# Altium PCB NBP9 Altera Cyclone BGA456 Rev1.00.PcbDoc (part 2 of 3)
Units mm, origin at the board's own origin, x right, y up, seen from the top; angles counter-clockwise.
Board outline 69 x 80.99 mm, 6 copper layers (Top Layer, MidLayer1, InternalPlane1, InternalPlane2, MidLayer2, Bottom Layer); 105 components, 269 nets, 899 pads, 453 vias.
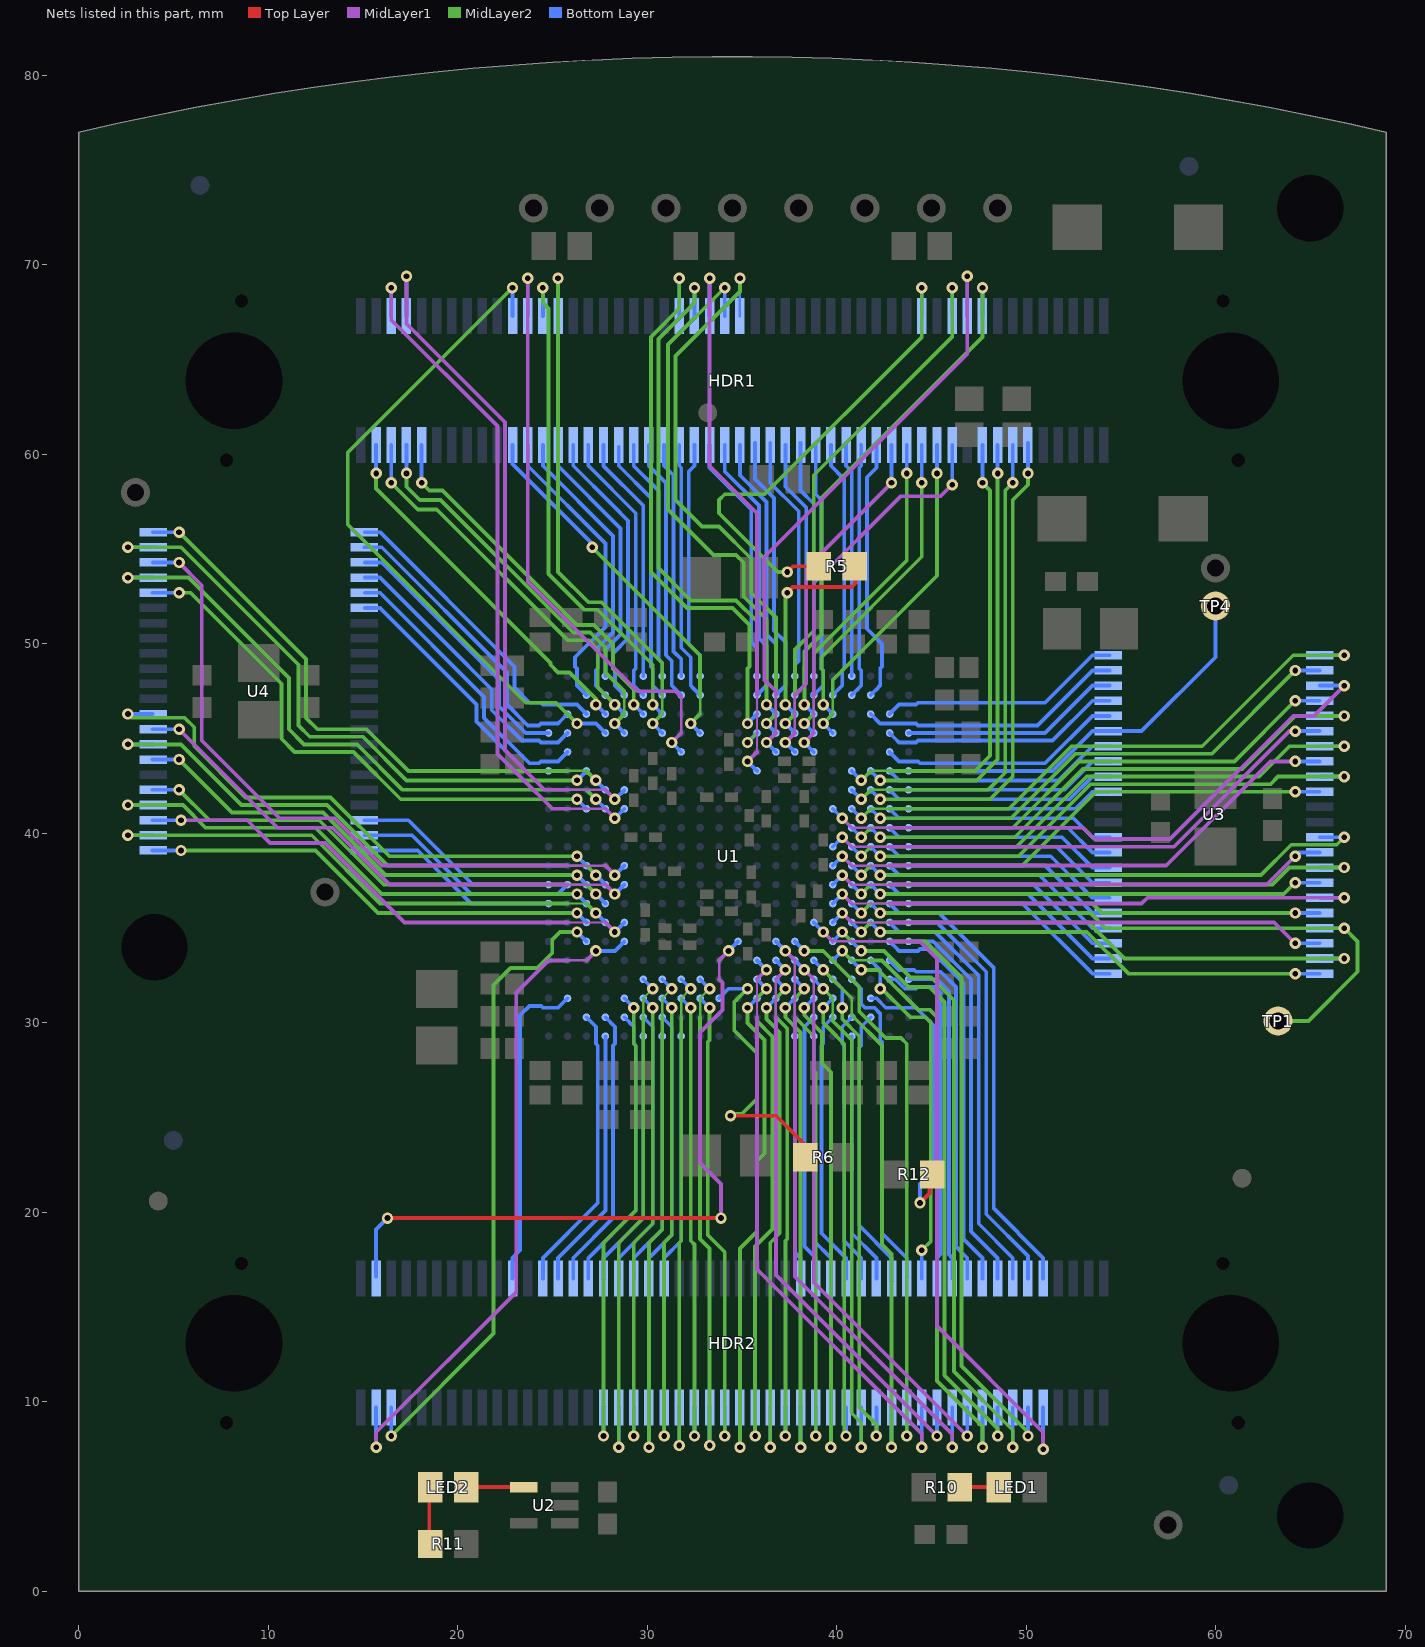
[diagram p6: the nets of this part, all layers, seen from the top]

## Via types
v1: diameter 0.6, hole 0.3, Top Layer to Bottom Layer, 453 vias

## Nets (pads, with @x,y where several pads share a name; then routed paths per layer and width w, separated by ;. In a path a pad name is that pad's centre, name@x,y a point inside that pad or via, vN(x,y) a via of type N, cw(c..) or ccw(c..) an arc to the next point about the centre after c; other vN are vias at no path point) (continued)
IO13: HDR2.33 U1.T3 | length 25.8
  MidLayer2 w0.2: v1(27.7,8.2) 27.7,18.4 29.4,20.1 29.4,28.8 29.3,28.9 v1(29.3,30.8)
  Bottom Layer w0.2: v1(27.7,8.2) HDR2.33@27.7,9.7 ; U1.T3@28.8,31.3 v1(29.3,30.8) v1@29.101,30.999
IO14: HDR2.35 U1.R4 | length 28
  MidLayer2 w0.127: 29.8,30.3 29.8,31.3 v1(30.3,31.8)
  MidLayer2 w0.2: v1(28.5,7.6) 28.5,18.4 29.8,19.7 29.8,30.3
  Bottom Layer w0.2: v1(28.5,7.6) HDR2.35@28.5,9.7 ; U1.R4@29.8,32.3 v1(30.3,31.8) v1@30.101,31.999
IO15: HDR2.37 U1.R3 | length 25.5
  MidLayer2 w0.2: v1(29.3,8.2) 29.3,18.4 30.3,19.4 v1(30.3,30.8)
  Bottom Layer w0.2: v1(29.3,8.2) HDR2.37@29.3,9.7 ; U1.R3@29.8,31.3 v1(30.3,30.8) v1@30.101,30.999
IO16: HDR2.39 U1.P4 | length 27.8
  MidLayer2 w0.127: 30.8,30.3 30.8,31.3 v1(31.3,31.8)
  MidLayer2 w0.2: v1(30.1,7.6) 30.1,18.4 30.8,19.1 30.8,30.3
  Bottom Layer w0.2: v1(30.1,7.6) HDR2.39@30.1,9.7 ; U1.P4@30.8,32.3 v1(31.3,31.8) v1@31.101,31.999
IO17: HDR2.41 U1.P3 | length 25.3
  MidLayer2 w0.2: v1(30.9,8.2) 30.9,18.4 31.3,18.8 v1(31.3,30.8)
  Bottom Layer w0.2: U1.P3@30.8,31.3 v1(31.3,30.8) v1@31.101,30.999 ; v1(30.9,8.2) HDR2.41@30.9,9.7
IO18: HDR2.43 U1.N4 | length 27.3
  MidLayer2 w0.127: 31.8,30.3 31.8,31.3 v1(32.3,31.8)
  MidLayer2 w0.2: v1(31.7,7.7) 31.7,18.4 31.8,18.5 31.8,30.3
  Bottom Layer w0.2: v1(31.7,7.7) HDR2.43@31.7,9.7 ; U1.N4@31.8,32.3 v1(32.3,31.8) v1@32.101,31.999
IO19: HDR2.45 U1.N3 | length 25.2
  MidLayer2 w0.2: v1(32.3,30.8) 32.3,18.5 32.5,18.3 v1(32.5,8.2)
  Bottom Layer w0.2: U1.N3@31.8,31.3 v1(32.3,30.8) v1@32.101,30.999 ; v1(32.5,8.2) HDR2.45@32.5,9.7
IO20: HDR2.47 U1.M4 | length 27.3
  MidLayer2 w0.127: 32.8,30.3 32.8,31.3 v1(33.3,31.8)
  MidLayer2 w0.203: 32.8,30.3 32.8,18.6 33.3,18.1 v1(33.3,7.7)
  Bottom Layer w0.2: U1.M4@32.8,32.3 v1(33.3,31.8) ; v1(33.3,7.7) HDR2.47@33.3,9.8
IO21: HDR2.49 U1.M3 | length 25.2
  MidLayer2 w0.203: v1(33.3,30.8) 33.3,29.1 33.2,29 33.2,18.8 34.1,17.9 v1(34.1,8.2)
  Bottom Layer w0.2: U1.M3@32.8,31.3 v1(33.3,30.8) ; v1(34.1,8.2) HDR2.49@34.1,9.7
IO22: HDR2.51 U1.J3 | length 26.9
  MidLayer2 w0.2: v1(34.9,7.6) 34.9,18.1 35.8,19 35.8,22.7 36.2,23.1 36.2,29.1 35.3,30 v1(35.3,30.8)
  Bottom Layer w0.2: v1(34.9,7.6) HDR2.51@34.9,9.7 ; v1(35.3,30.8) U1.J3@35.8,31.3
IO23: HDR2.53 U1.J4 | length 26.7
  MidLayer2 w0.127: 35.8,30.1 35.8,31.3
  MidLayer2 w0.2: v1(35.7,8.2) 35.7,18.2 36.6,19.1 36.6,29.3 35.8,30.1 ; 35.8,31.3 v1(36.3,31.8)
  Bottom Layer w0.2: v1(35.7,8.2) HDR2.53@35.7,9.7 ; U1.J4@35.8,32.3 v1(36.3,31.8)
IO24: HDR2.55 U1.H3 | length 26.8
  MidLayer2 w0.2: v1(36.3,30.8) 36.3,30.2 37,29.5 37,18.9 36.5,18.4 v1(36.5,7.6)
  Bottom Layer w0.2: v1(36.5,7.6) HDR2.55@36.5,9.7 ; v1@36.5,31 v1(36.3,30.8) U1.H3@36.8,31.3
IO25: HDR2.57 U1.H4 | length 26.6
  MidLayer2 w0.127: 36.8,30.3 36.8,31.3
  MidLayer2 w0.2: 36.8,30.3 37.4,29.7 37.4,18.6 37.3,18.5 v1(37.3,8.2) ; 36.8,31.3 v1(37.3,31.8)
  Bottom Layer w0.2: U1.H4@36.8,32.3 v1(37.3,31.8) v1@37.101,31.999 ; v1(37.3,8.2) HDR2.57@37.3,9.7
IO26: HDR2.59 U1.G3 | length 26.3
  MidLayer2 w0.2: v1(37.3,30.8) 37.3,30.3 38.1,29.5 v1(38.1,7.6)
  Bottom Layer w0.2: v1(37.3,30.8) U1.G3@37.8,31.3 ; v1(38.1,7.6) HDR2.59@38.1,9.7
IO27: HDR2.61 U1.G4 | length 26.8
  MidLayer2 w0.127: 37.8,30.3 37.8,31.3
  MidLayer2 w0.2: 37.8,30.3 38.8,29.3 38.8,27.5 38.9,27.4 v1(38.9,8.2) ; 37.8,31.3 v1(38.3,31.8)
  Bottom Layer w0.2: U1.G4@37.8,32.3 v1(38.3,31.8) v1@38.101,31.999 ; v1(38.9,8.2) HDR2.61@38.9,9.7
IO28: HDR2.63 U1.F3 | length 26.9
  MidLayer2 w0.2: v1(38.3,30.8) 38.3,30.4 39.225,29.475 39.225,27.875 39.7,27.4 v1(39.7,7.6)
  Bottom Layer w0.2: v1(38.3,30.8) v1@38.5,31 ; v1(38.3,30.8) U1.F3@38.8,31.3 ; v1(39.7,7.6) HDR2.63@39.7,9.7
IO29: HDR2.65 U1.E3 | length 25.6
  MidLayer2 w0.2: v1(39.3,30.8) 39.3,30 39.6,29.7 40.4,28.9 40.4,8.3 v1(40.5,8.2)
  Bottom Layer w0.2: v1@39.499,31 v1(39.3,30.8) U1.E3@39.8,31.3 ; v1(40.5,8.2) HDR2.65@40.5,9.7
IO30: HDR2.67 U1.F4 | length 28.1
  MidLayer2 w0.127: 39.8,30.3 39.8,31.3
  MidLayer2 w0.2: v1(39.3,31.8) 39.8,31.3 ; 39.8,30.3 39.8,30.1 40.8,29.1 40.8,9.4 41.3,8.9 v1(41.3,7.6)
  Bottom Layer w0.2: U1.F4@38.8,32.3 v1(39.3,31.8) v1@39.101,31.999 ; v1(41.3,7.6) HDR2.67@41.3,9.7
IO31: HDR2.69 U1.E4 | length 26.6
  MidLayer2 w0.2: v1(40.3,30.8) 40.3,30.2 41.2,29.3 41.2,9.7 42.1,8.8 v1(42.1,8.2)
  Bottom Layer w0.2: U1.E4@39.8,32.3 40.1,32 ; 40.101,31.999 40.3,31.8 v1(40.3,30.8) ; v1(42.1,8.2) HDR2.69@42.1,9.7
IO32: HDR2.71 U1.F5 | length 29.8
  MidLayer2 w0.127: 40.8,30.4 40.8,31.3
  MidLayer2 w0.2: v1(39.3,32.8) 40.8,31.3 ; 40.8,30.4 42.4,28.8 42.4,18.3 42.9,17.8 v1(42.9,7.6)
  Bottom Layer w0.2: U1.F5@38.8,33.3 v1(39.3,32.8) v1@39.101,32.999 ; v1(42.9,7.6) HDR2.71@42.9,9.7
IO33: HDR2.73 U1.G6 | length 31.6
  MidLayer2 w0.2: v1(38.3,33.8) 39.3,33.8 ; 39.1,33.8 39.3,33.8 ; v1(43.7,8.2) 43.7,28.9 43.4,29.2 42.6,29.2 41.2,30.6 41.2,31.9 40.3,32.8 39.3,33.8
  Bottom Layer w0.2: U1.G6@37.8,34.3 v1(38.3,33.8) v1@38.101,33.999 ; v1(43.7,8.2) HDR2.73@43.7,9.7
IO34: HDR2.75 U1.J5 | length 32.1
  MidLayer1 w0.127: 35.8,30.3 35.8,32.3
  MidLayer1 w0.2: 35.8,30.3 35.8,17 44.5,8.3 v1(44.5,7.6) ; 35.8,32.3 v1(36.3,32.8)
  Bottom Layer w0.2: U1.J5@35.8,33.3 v1(36.3,32.8) v1@36.101,32.999 ; v1(44.5,7.6) HDR2.75@44.5,9.7
IO35: HDR2.77 U1.H5 | length 30.8
  MidLayer1 w0.127: 36.8,30.3 36.8,32.3
  MidLayer1 w0.2: 36.8,30.3 36.8,16.7 v1(45.3,8.2) ; 36.8,32.3 v1(37.3,32.8)
  Bottom Layer w0.2: U1.H5@36.8,33.3 v1(37.3,32.8) v1@37.101,32.999 ; v1(45.3,8.2) HDR2.77@45.3,9.7
JIOA0: HDR1.3 U1.U18 | length 19.6
  MidLayer2 w0.2: v1@15.7,59.1 15.7,58.2 24.9,49 24.9,48.9 25.3,48.5 25.9,48.5 27.3,47.1 v1(27.3,46.8)
  Bottom Layer w0.2: v1@15.7,59.1 HDR1.3@15.7,60.5 ; v1(27.3,46.8) U1.U18@27.8,46.3
  other v1: 15.7,59
JIOA1: HDR1.5 U1.T18 | length 20.5
  MidLayer2 w0.2: v1(16.5,58.5) 17.9,57.1 18.9,57.1 25.8,50.2 26.9,50.2 27.4,49.7 27.4,47.7 v1(28.3,46.8)
  Bottom Layer w0.2: v1(16.5,58.5) HDR1.5@16.5,60.5 ; v1(28.3,46.8) U1.T18@28.8,46.3
JIOA2: HDR1.7 U1.T17 | length 21.5
  MidLayer2 w0.127: 28.8,46.3 28.8,47.3
  MidLayer2 w0.2: v1(17.3,59) 17.3,58.3 18,57.6 19.1,57.6 26.1,50.6 27,50.6 27.8,49.8 27.8,48.5 28.8,47.5 28.8,47.3 ; v1(28.3,45.8) 28.8,46.3
  Bottom Layer w0.2: v1(17.3,59) HDR1.7@17.3,60.5 ; v1(28.3,45.8) U1.T17@28.8,45.3
JIOA3: HDR1.9 U1.R18 | length 20
  MidLayer2 w0.2: v1(18.1,58.5) 18.5,58.1 19.2,58.1 26.3,51 27.2,51 28.2,50 28.2,48.7 29.3,47.6 v1(29.3,46.8)
  Bottom Layer w0.2: v1(18.1,58.5) HDR1.9@18.1,60.5 ; v1(29.3,46.8) U1.R18@29.8,46.3
JIOB0: HDR1.83 U1.D15 | length 24.9
  MidLayer2 w0.127: 41.8,43.3 42.8,43.3
  MidLayer2 w0.2: v1(41.3,42.8) 41.8,43.3 ; 42.8,43.3 47.3,43.3 48.1,44.1 48.1,58.1 v1(47.7,58.5)
  Bottom Layer w0.2: U1.D15@40.8,43.3 v1(41.3,42.8) v1@41.101,42.999 ; v1(47.7,58.5) HDR1.83@47.7,60.5
JIOB1: HDR1.85 U1.C15 | length 24.2
  MidLayer2 w0.2: v1(42.3,42.8) 47.4,42.8 48.5,43.9 v1(48.5,59)
  Bottom Layer w0.2: U1.C15@41.8,43.3 v1(42.3,42.8) v1@42.101,42.999 ; v1(48.5,59) HDR1.85@48.5,60.5
JIOB2: HDR1.87 U1.D14 | length 26.6
  MidLayer2 w0.127: 41.8,42.3 42.8,42.3
  MidLayer2 w0.2: v1(41.3,41.8) 41.8,42.3 ; 42.8,42.3 48,42.3 48.9,43.2 48.9,58.1 v1(49.3,58.5)
  Bottom Layer w0.2: U1.D14@40.8,42.3 v1(41.3,41.8) v1@41.101,41.999 ; v1(49.3,58.5) HDR1.87@49.3,60.5
JIOB3: HDR1.89 U1.C14 | length 26.4
  MidLayer2 w0.2: v1(42.3,41.8) 48.1,41.8 49.3,43 49.3,57.6 50.1,58.4 v1(50.1,59)
  Bottom Layer w0.2: U1.C14@41.8,42.3 v1(42.3,41.8) v1@42.101,41.999 ; v1(50.1,59) HDR1.89@50.1,60.6
KBCLOCK: HDR1.22 U1.U17 | length 35.8
  MidLayer2 w0.2: v1(22.9,68.8) 14.2,60.1 14.2,56.3 23.6,46.9 25.2,46.9 v1(26.3,45.8)
  Bottom Layer w0.2: HDR1.22@22.9,67.3 v1(22.9,68.8) ; v1(26.3,45.8) 27.3,45.8 U1.U17@27.8,45.3
KBDATA: HDR1.24 U1.N16 | length 31.9
  MidLayer1 w0.127: 31.8,45.3 31.8,47.2
  MidLayer1 w0.2: v1(23.7,69.3) 23.7,62.2 23.7,53.3 29.5,47.5 31.5,47.5 31.8,47.2 ; v1(31.3,44.8) 31.8,45.3
  Bottom Layer w0.2: HDR1.24@23.7,67.3 v1(23.7,69.3) ; v1(31.3,44.8) U1.N16@31.8,44.3
LCD_BCKL: HDR2.22 U1.W3 | length 17
  Bottom Layer w0.2: HDR2.22@22.9,16.5 22.9,17.6 23.3,18 23.3,30.4 23.8,30.9 24.4,30.9 24.5,30.8 25.3,30.8 U1.W3@25.8,31.3
LCD_E: HDR2.26 U1.V2 | length 15.2
  Bottom Layer w0.2: HDR2.26@24.5,16.5 24.5,17.6 27.2,20.3 27.4,20.5 27.4,28.8 27.3,28.9 27.3,29.8 U1.V2@26.8,30.3
LED0: HDR2.60 U1.G1 | length 13.2
  Bottom Layer w0.2: 37.8,28.7 U1.G1@37.8,29.3 ; 37.8,28.875 37.8,17.9 38.1,17.6 HDR2.60@38.1,16.4
LED1: HDR2.62 U1.F2 | length 14.3
  Bottom Layer w0.2: U1.F2@38.8,30.3 38.3,29.8 38.3,18.2 38.9,17.6 HDR2.62@38.9,16.5
LED2: HDR2.64 U1.F1 | length 13.5
  Bottom Layer w0.2: 38.8,28.6 U1.F1@38.8,29.3 ; 38.8,28.875 38.8,18.5 39.7,17.6 HDR2.64@39.7,16.4
LED3: HDR2.66 U1.E2 | length 14.6
  Bottom Layer w0.2: U1.E2@39.8,30.3 39.3,29.8 39.3,28.9 39.2,28.8 39.2,18.9 40.5,17.6 HDR2.66@40.5,16.5
LED4: HDR2.68 U1.D2 | length 14.4
  Bottom Layer w0.2: U1.D2@40.8,30.3 40.3,29.8 40.3,28.9 40.4,28.8 40.4,18.5 41.3,17.6 HDR2.68@41.3,16.5
LED5: HDR2.70 U1.D1 | length 13.4
  Bottom Layer w0.2: 40.8,28.8 U1.D1@40.8,29.3 ; 40.8,28.875 40.8,18.9 42.1,17.6 HDR2.70@42.1,16.5
LED6: HDR2.72 U1.C2 | length 14.9
  Bottom Layer w0.2: U1.C2@41.8,30.3 41.3,29.8 41.3,28.8 41.2,28.7 41.2,19.3 42.9,17.6 HDR2.72@42.9,16.4
LED7: HDR2.74 U1.D4 | length 17.2
  Bottom Layer w0.2: U1.D4@40.8,32.3 41.1,32 ; 41.101,31.999 41.3,31.8 41.3,31 41.5,30.8 42,30.8 42.3,30.5 42.3,29.1 42.4,29 42.4,18.9 43.7,17.6 HDR2.74@43.7,16.6
MOUSECLOCK: HDR1.26 U1.P18 | length 27
  MidLayer2 w0.2: v1(24.5,68.8) 24.5,68 24.8,67.7 24.8,53.7 26.7,51.8 27.4,51.8 30.3,48.9 v1(30.3,46.8)
  Bottom Layer w0.2: HDR1.26@24.5,67.3 24.5,67.4 v1(24.5,68.8) ; v1(30.3,46.8) U1.P18@30.8,46.3
MOUSEDATA: HDR1.28 U1.P17 | length 29.1
  MidLayer2 w0.127: 30.8,46.3 30.8,47.3
  MidLayer2 w0.2: v1(25.3,69.3) 25.3,66 25.3,53.8 26.9,52.2 27.6,52.2 30.8,49 30.8,47.3 ; v1(30.3,45.8) 30.8,46.3
  Bottom Layer w0.2: HDR1.28@25.3,67.3 v1(25.3,69.3) ; v1(30.3,45.8) U1.P17@30.8,45.3
NetLED1_1: LED1.1 R10.2 | length 2.1
  Top Layer w0.2: R10.2@46.5,5.5 LED1.1@48.6,5.5
NetLED2_1: LED2.1 R11.1 | length 3.1
  Top Layer w0.2: R11.1@18.5,2.4 LED2.1@18.5,5.5
NetLED2_2: LED2.2 U2.4 | length 3
  Top Layer w0.2: LED2.2@20.45,5.5 U2.4@23.5,5.5
NetR6_1: R6.1 U1.L3 | length 15.3
  Top Layer w0.2: v1(34.4,25.1) 36.8,25.1 38,23.9 38.4,23.5 R6.1@38.4,22.9
  MidLayer2 w0.2: v1@34.4,25.2 35,25.2 35.8,26 35.8,28.4 34.6,29.6 34.6,31.1 34.7,31.2 ; 34.725,31.2 34.725,31.225 v1(35.3,31.8)
  Bottom Layer w0.2: U1.L3@33.8,31.3 34.3,31.8 v1(35.3,31.8)
NetR12_1: R12.1 U1.C3 | length 15.3
  Top Layer w0.2: v1(44.4,20.5) 44.9,21 R12.1@44.9,22
  Bottom Layer w0.2: U1.C3@41.8,31.3 42.1,31.3 42.6,30.8 44.2,30.8 45.1,29.9 45.1,22.2 44.4,21.5 v1(44.4,20.5)
NEXUS_TCK: HDR1.82 U1.H16 | length 32.3
  MidLayer1 w0.127: 36.8,45.3 36.8,47.3
  MidLayer1 w0.2: v1(36.3,44.8) 36.8,45.3 ; 36.8,47.3 36.8,47.5 36.2,48.1 36.2,54.6 46.9,65.3 v1(46.9,69.4)
  Bottom Layer w0.2: v1(36.3,44.8) U1.H16@36.8,44.3 ; HDR1.82@46.9,67.3 v1(46.9,69.4)
NEXUS_TDI: HDR1.84 U1.F18 | length 28.1
  MidLayer2 w0.2: v1(38.3,46.8) 38.3,49.6 39.2,50.5 39.2,57.7 41.2,59.7 47.7,66.2 v1(47.7,68.8)
  Bottom Layer w0.2: v1(38.3,46.8) U1.F18@38.8,46.3 ; HDR1.84@47.7,67.3 v1(47.7,68.8)
NEXUS_TDO: HDR1.76 R5.1 | length 25.7
  Top Layer w0.2: v1(37.4,53.8) 37.7,54.1 R5.1@39,54.1
  MidLayer2 w0.2: v1(37.4,53.8) 36.9,53.8 33.8,56.9 33.8,57.6 34.1,57.9 36.2,57.9 44.5,66.2 v1(44.5,68.8)
  Bottom Layer w0.2: HDR1.76@44.5,67.3 v1(44.5,68.8)
NEXUS_TDO#: R5.2 U1.G18 | length 11.8
  Top Layer w0.2: v1(37.4,52.7) 37.7,53 40.8,53 41,53.2 R5.2@41,54.5
  MidLayer2 w0.2: v1(37.3,46.8) 37.3,52.6 v1(37.4,52.7)
  Bottom Layer w0.2: v1(37.3,46.8) U1.G18@37.8,46.3
NEXUS_TMS: HDR1.80 U1.G17 | length 29.1
  MidLayer2 w0.127: 37.8,46.3 37.8,47.3
  MidLayer2 w0.2: v1(37.3,45.8) 37.8,46.3 ; 37.8,47.3 37.8,49.7 38.8,50.7 38.8,58.9 46.1,66.2 v1(46.1,68.8)
  Bottom Layer w0.2: v1@37.5,45.6 v1(37.3,45.8) U1.G17@37.8,45.3 ; HDR1.80@46.1,67.3 v1(46.1,68.8)
RAM0_DATA0: HDR2.42 U1.N1 | length 13.4
  Bottom Layer w0.2: HDR2.42@30.9,16.5 30.9,17.6 31.8,18.5 31.8,28.875 ; 31.8,28.6 U1.N1@31.8,29.3
RAM0_DATA1: HDR2.40 U1.P2 | length 14.6
  Bottom Layer w0.2: HDR2.40@30.1,16.4 30.1,17.6 31.3,18.8 31.3,29.8 U1.P2@30.8,30.3
RAM0_DATA2: HDR2.38 U1.P1 | length 13.5
  Bottom Layer w0.2: HDR2.38@29.3,16.5 29.3,17.6 30,18.3 30.8,19.1 30.8,28.875 ; 30.8,28.8 U1.P1@30.8,29.3
RAM0_DATA3: HDR2.36 U1.R2 | length 14.8
  Bottom Layer w0.2: HDR2.36@28.5,16.5 28.5,17.6 30.3,19.4 30.3,27.5 30.3,29.8 U1.R2@29.8,30.3
RAM0_DATA4: HDR2.34 U1.R1 | length 13.6
  Bottom Layer w0.2: HDR2.34@27.7,16.5 27.7,17.6 29.8,19.7 29.8,28.875 ; 29.8,28.9 U1.R1@29.8,29.3
RAM0_DATA5: HDR2.32 U1.T2 | length 15.4
  Bottom Layer w0.2: HDR2.32@26.9,16.5 26.9,17.6 29.4,20.1 29.4,28.8 29.3,28.9 29.3,29.8 ; U1.T2@28.8,30.3 29.3,29.8 ; 29.101,29.999 29.3,29.8
RAM0_DATA6: HDR2.30 U1.U2 | length 15.2
  Bottom Layer w0.2: HDR2.30@26.1,16.5 26.1,17.6 28.2,19.7 28.2,28.8 28.3,28.9 28.3,29.8 ; U1.U2@27.8,30.3 28.3,29.8 ; 28.101,29.999 28.3,29.8
RAM0_DATA7: HDR2.28 U1.U1 | length 13.9
  Bottom Layer w0.2: HDR2.28@25.3,16.5 25.3,17.6 27.8,20.1 27.8,27.5 27.8,28.875 ; 27.8,28.8 U1.U1@27.8,29.3
RAM0_OE: HDR1.41 U1.N20 | length 12.6
  Bottom Layer w0.2: HDR1.41@30.9,60.5 30.9,59.4 31.2,59.1 31.4,58.9 31.4,49.6 31.8,49.2 U1.N20@31.8,48.3
RAM0_WE: HDR1.79 U1.F16 | length 20.9
  MidLayer1 w0.127: 38.8,45.3 38.8,47.3
  MidLayer1 w0.2: v1(38.3,44.8) 38.8,45.3 ; 38.8,47.3 38.8,53.2 43.4,57.8 45.5,57.8 v1(46.1,58.4)
  Bottom Layer w0.2: v1(38.3,44.8) U1.F16@38.8,44.3 ; v1(46.1,58.4) HDR1.79@46.1,60.5
RAM1_DATA0: HDR1.45 U1.M20 | length 12.6
  Bottom Layer w0.2: HDR1.45@32.5,60.5 32.5,59.4 32.2,59.1 32.2,50 32.8,49.4 32.8,49 U1.M20@32.8,48.3
RAM1_DATA1: HDR1.49 U1.J19 | length 14.5
  Bottom Layer w0.2: HDR1.49@34.1,60.5 34.1,59.1 35.9,57.3 35.9,50.3 36.3,49.9 36.3,47.8 36.2,47.7 ; U1.J19@35.8,47.3 36.2,47.7 ; 36.101,47.601 36.2,47.7
RAM1_DATA2: HDR1.53 U1.H19 | length 14.2
  Bottom Layer w0.2: HDR1.53@35.7,60.6 35.7,58.7 36.7,57.7 36.7,50.7 37.3,50.1 37.3,47.8 37.101,47.601 ; U1.H19@36.8,47.3 37.1,47.6
RAM1_DATA3: HDR1.57 U1.G19 | length 13.9
  Bottom Layer w0.2: HDR1.57@37.3,60.5 37.3,58.3 38.4,57.2 38.4,48.9 38.3,48.8 38.3,47.8 38.101,47.601 ; U1.G19@37.8,47.3 38.1,47.6
RAM1_DATA4: HDR1.55 U1.G20 | length 13
  Bottom Layer w0.2: HDR1.55@36.5,60.6 36.5,58.5 38,57 38,49.1 37.8,48.9 U1.G20@37.8,48.3
RAM1_DATA5: HDR1.51 U1.H20 | length 13
  Bottom Layer w0.2: HDR1.51@34.9,60.5 34.9,60.4 34.9,58.9 36.3,57.5 36.3,50.5 36.8,50 U1.H20@36.8,48.3
RAM1_DATA6: HDR1.47 U1.J20 | length 13.2
  Bottom Layer w0.2: HDR1.47@33.3,60.5 33.3,59.3 34.1,58.5 35.5,57.1 35.5,50.1 35.8,49.8 U1.J20@35.8,48.3
RAM1_DATA7: HDR1.43 U1.M19 | length 13.8
  Bottom Layer w0.2: HDR1.43@31.7,60.5 31.7,59.4 31.8,59.3 31.8,49.8 32.3,49.3 32.3,47.8 32.4,47.7 ; 32.5,47.6 32.4,47.7 ; U1.M19@32.8,47.3 32.4,47.7
RAM1_OE: HDR1.39 U1.N19 | length 13.9
  Bottom Layer w0.2: HDR1.39@30.1,60.5 30.1,59.4 31,58.5 31,49.4 31.3,49.1 31.3,47.8 U1.N19@31.8,47.3
RAM1_WE: HDR1.61 U1.F19 | length 13.7
  Bottom Layer w0.2: U1.F19@38.7,47.3 U1.F19@38.8,47.3 39.3,47.8 39.3,48.6 39.2,48.7 39.2,57.6 38.9,57.9 HDR1.61@38.9,60.5
RAM_ADDR0: HDR1.21 U1.M17 | length 20
  MidLayer2 w0.127: 32.8,46.3 32.8,47.3
  MidLayer2 w0.2: v1(27.1,55.1) 28,54.2 32.8,49.4 32.8,47.3 ; v1(32.3,45.8) 32.8,46.3
  Bottom Layer w0.2: HDR1.21@22.9,60.5 22.9,59.5 27.1,55.3 v1(27.1,55.1) ; v1@32.5,45.6 v1(32.3,45.8) U1.M17@32.8,45.3
RAM_ADDR1: HDR1.25 U1.U19 | length 15.3
  Bottom Layer w0.2: HDR1.25@24.5,60.5 24.5,59.4 28.2,55.7 28.2,50.6 27.4,49.8 27.4,48.7 27.3,48.6 27.3,47.8 U1.U19@27.8,47.3
RAM_ADDR2: HDR1.29 U1.T19 | length 15
  Bottom Layer w0.2: HDR1.29@26.1,60.5 26.1,59.4 28.2,57.3 29,56.5 29,50.3 28.2,49.5 28.2,48.7 28.3,48.6 28.3,47.8 U1.T19@28.8,47.3
RAM_ADDR3: HDR1.33 U1.R20 | length 13.1
  Bottom Layer w0.2: HDR1.33@27.7,60.5 27.7,59.4 29.8,57.3 U1.R20@29.8,48.3
RAM_ADDR4: HDR1.65 U1.D20 | length 12.3
  Bottom Layer w0.2: HDR1.65@40.5,60.5 40.5,59.4 40.8,59.1 U1.D20@40.8,48.3
RAM_ADDR5: HDR1.69 U1.C19 | length 14.1
  Bottom Layer w0.2: U1.C19@41.8,47.3 42.2,47.7 ; 42.101,47.601 42.3,47.8 42.3,48.7 42.4,48.8 42.4,50 41.6,50.8 41.6,58.8 42.1,59.3 HDR1.69@42.1,60.5
RAM_ADDR6: HDR1.73 U1.F17 | length 17.6
  MidLayer2 w0.127: 38.8,46.3 38.8,47.3
  MidLayer2 w0.2: v1(38.3,45.8) 38.8,46.3 ; 38.8,47.3 38.8,49.5 39.9,50.6 43.7,54.4 v1(43.7,59)
  Bottom Layer w0.2: v1(38.3,45.8) U1.F17@38.8,45.3 ; v1(43.7,59) HDR1.73@43.7,60.5
RAM_ADDR7: HDR1.77 U1.E17 | length 17.9
  MidLayer2 w0.127: 39.8,46.3 39.8,47.3
  MidLayer2 w0.2: v1(39.3,45.8) 39.8,46.3 ; 39.8,47.3 39.8,48.1 41.1,49.4 45.3,53.6 45.3,58.4 v1(45.3,59)
  Bottom Layer w0.2: v1(39.3,45.8) U1.E17@39.8,45.3 ; v1(45.3,59) HDR1.77@45.3,60.5
RAM_ADDR8: HDR1.75 U1.E18 | length 16.6
  MidLayer2 w0.2: v1(39.3,46.8) 39.3,48.6 39.2,48.7 39.2,49.3 44.5,54.6 v1@44.5,58.5
  Bottom Layer w0.2: v1(39.3,46.8) U1.E18@39.8,46.3 ; v1(44.5,58.5) HDR1.75@44.5,60.5
RAM_ADDR9: HDR1.71 U1.G16 | length 18.7
  MidLayer1 w0.127: 37.8,45.3 37.8,47.3
  MidLayer1 w0.2: v1(37.3,44.8) 37.8,45.3 ; 37.8,47.3 38.4,47.9 38.4,54 40.2,55.8 v1(42.9,58.5)
  Bottom Layer w0.2: v1(37.3,44.8) U1.G16@37.8,44.3 ; v1(42.9,58.5) HDR1.71@42.9,60.5
RAM_ADDR10: HDR1.67 U1.D19 | length 13.6
  Bottom Layer w0.2: U1.D19@40.8,47.3 41.2,47.7 ; 41.101,47.601 41.2,47.7 ; HDR1.67@41.3,60.5 41.3,59.4 41.2,59.3 41.2,48.7 41.3,48.6 41.3,47.8 41.2,47.7
RAM_ADDR11: HDR1.63 U1.E19 | length 13.7
  Bottom Layer w0.2: HDR1.63@39.7,60.5 39.7,59.4 40.4,58.7 40.4,48.7 40.3,48.6 40.3,47.8 U1.E19@39.8,47.3
RAM_ADDR12: HDR1.59 U1.F20 | length 12.6
  Bottom Layer w0.2: HDR1.59@38.1,60.6 38.1,58.1 38.8,57.4 U1.F20@38.8,48.3
RAM_ADDR13: HDR1.35 U1.P19 | length 14.1
  Bottom Layer w0.2: HDR1.35@28.5,60.4 28.5,59.4 30.2,57.7 30.2,48.8 30.3,48.7 30.3,47.8 U1.P19@30.8,47.3
RAM_ADDR14: HDR1.31 U1.R19 | length 14.5
  Bottom Layer w0.2: HDR1.31@26.9,60.5 26.9,59.4 29.4,56.9 29.4,48.7 29.3,48.6 29.3,47.8 U1.R19@29.8,47.3
RAM_ADDR15: HDR1.27 U1.U20 | length 13.9
  Bottom Layer w0.2: HDR1.27@25.3,60.5 25.3,59.4 28.6,56.1 28.6,50.5 27.8,49.7 U1.U20@27.8,48.3
RAM_ADDR16: HDR1.23 U1.V19 | length 15.8
  Bottom Layer w0.2: HDR1.23@23.7,60.5 23.7,59.4 27.8,55.3 27.8,50.9 26.2,49.3 26.2,48.8 26.3,48.7 26.3,47.8 U1.V19@26.8,47.3
RAM_CS: HDR1.37 U1.P20 | length 12.8
  Bottom Layer w0.2: HDR1.37@29.3,60.5 29.3,59.4 30.6,58.1 30.6,49.2 30.8,49 U1.P20@30.8,48.3
RED0: HDR1.6 U1.T13 | length 37
  MidLayer1 w0.127: 25.8,41.3 27.8,41.3
  MidLayer1 w0.2: v1(16.5,68.8) 16.5,67.1 22.1,61.5 22.1,44.2 23.4,42.9 25,41.3 25.8,41.3 ; 27.8,41.3 v1(28.3,40.8)
  Bottom Layer w0.2: HDR1.6@16.5,67.3 v1(16.5,68.8) ; v1@28.499,40.999 v1(28.3,40.8) U1.T13@28.8,41.3
RED1: HDR1.8 U1.T14 | length 37.1
  MidLayer1 w0.127: 25.8,42.3 27.8,42.3
  MidLayer1 w0.2: v1(17.3,69.4) 17.3,66.9 22.5,61.7 22.5,44.4 24.6,42.3 25.8,42.3 ; 27.8,42.3 v1(28.3,41.8)
  Bottom Layer w0.2: HDR1.8@17.3,67.3 v1(17.3,69.4) ; v1@28.499,41.999 v1(28.3,41.8) U1.T14@28.8,42.3
REF_CLK: HDR2.4 U1.K6 | length 37
  Top Layer w0.2: v1(16.3,19.7) v1(33.9,19.7)
  MidLayer1 w0.127: 33.8,32.3 33.8,33.3
  MidLayer1 w0.2: 33.8,32.3 33.975,32.125 33.975,30.675 32.8,29.5 32.8,22.6 33.9,21.5 v1(33.9,19.7) ; 33.8,33.3 v1(34.3,33.8)
  Bottom Layer w0.2: HDR2.4@15.7,16.6 15.7,19.1 v1(16.3,19.7) ; v1(34.3,33.8) U1.K6@34.8,34.3
SCL: HDR2.5 U1.V6 | length 34.2
  MidLayer2 w0.2: v1(16.5,8.2) 21.9,13.6 21.9,32 22.8,32.9 24.2,32.9 25,33.7 25,34.4 25.4,34.8 v1(26.3,34.8)
  Bottom Layer w0.2: v1(16.5,8.2) HDR2.5@16.5,9.7 ; v1(26.3,34.8) U1.V6@26.8,34.3
SDA: HDR2.3 U1.T6 | length 36
  MidLayer1 w0.127: 25.8,33.3 26.8,33.3
  MidLayer1 w0.2: v1(15.7,7.6) 15.7,8.4 23.1,15.8 23.1,31.6 24.8,33.3 25.8,33.3 ; 26.8,33.3 v1(27.3,33.8)
  Bottom Layer w0.2: v1(15.7,7.6) HDR2.3@15.7,9.7 ; v1(27.3,33.8) 28.3,33.8 U1.T6@28.8,34.3
SP0: HDR2.79 U1.H6 | length 32.9
  MidLayer1 w0.127: 37.8,30.3 37.8,33.3
  MidLayer1 w0.2: v1(37.3,33.8) 37.8,33.3 ; 37.8,30.3 37.8,16.6 46.1,8.3 v1(46.1,7.6)
  Bottom Layer w0.2: U1.H6@36.8,34.3 v1(37.3,33.8) v1@37.101,33.999 ; v1(46.1,7.6) HDR2.79@46.1,9.7
SP1: HDR2.81 U1.G5 | length 30.7
  MidLayer1 w0.127: 38.8,30.3 38.8,32.3
  MidLayer1 w0.2: v1(38.3,32.8) 38.8,32.3 ; 38.8,30.3 38.8,16.3 v1(46.9,8.2)
  Bottom Layer w0.2: U1.G5@37.8,33.3 v1(38.3,32.8) v1@38.101,32.999 ; v1(46.9,8.2) HDR2.81@46.9,9.7
SP2: HDR2.83 U1.D5 | length 31.8
  MidLayer2 w0.2: v1(41.3,32.8) 42.2,32.8 44.3,30.7 44.9,30.7 45.3,30.3 45.3,11.1 47.7,8.7 v1(47.7,7.6)
  Bottom Layer w0.2: U1.D5@40.8,33.3 v1(41.3,32.8) v1@41.101,32.999 ; v1(47.7,7.6) HDR2.83@47.7,9.7
SP3: HDR2.85 U1.E5 | length 32.8
  MidLayer2 w0.127: 40.8,33.3 41.8,33.3
  MidLayer2 w0.2: v1(40.3,33.8) 40.8,33.3 ; 41.8,33.3 42.4,33.3 43.3,32.4 43.8,31.9 44.9,31.9 45.7,31.1 45.7,11.4 48.5,8.6 v1(48.5,8.2)
  Bottom Layer w0.2: U1.E5@39.8,33.3 v1(40.3,33.8) ; v1(48.5,8.2) HDR2.85@48.5,9.7
SP4: HDR2.87 U1.D6 | length 33.9
  MidLayer2 w0.2: v1(41.3,33.8) 42.5,33.8 43.9,32.4 45,32.4 46.2,31.2 46.2,11.6 49.3,8.5 v1(49.3,7.6)
  Bottom Layer w0.2: U1.D6@40.8,34.3 v1(41.3,33.8) v1@41.101,33.999 ; v1(49.3,7.6) HDR2.87@49.3,9.7
SP5: HDR2.89 U1.E6 | length 35.2
  MidLayer2 w0.127: 40.8,34.3 42.8,34.3
  MidLayer2 w0.2: v1(40.3,34.8) 40.8,34.3 ; 42.8,34.3 44.7,34.3 46.6,32.4 46.6,11.9 50.1,8.4 v1(50.1,8.2)
  Bottom Layer w0.2: U1.E6@39.8,34.3 v1(40.3,34.8) ; v1(50.1,8.2) HDR2.89@50.1,9.7
SP6: HDR2.91 U1.F7 | length 38
  MidLayer1 w0.127: 39.8,34.3 42.8,34.3
  MidLayer1 w0.2: v1(39.3,34.8) 39.8,34.3 ; 42.8,34.3 44.4,34.3 45.3,33.4 45.3,14 50.9,8.4 v1(50.9,7.5)
  Bottom Layer w0.2: U1.F7@38.8,35.3 v1(39.3,34.8) v1@39.101,34.999 ; v1(50.9,7.5) HDR2.91@50.9,9.7
SP7: HDR2.90 U1.A7 | length 22.3
  Bottom Layer w0.2: U1.A7@43.8,35.3 45.3,35.3 47.9,32.7 47.9,19.9 50.1,17.7 HDR2.90@50.1,16.5
SP8: HDR2.92 U1.B8 | length 24.7
  Bottom Layer w0.2: U1.B8@42.8,36.3 43.3,35.8 ; 43.101,35.999 43.3,35.8 45.4,35.8 48.3,32.9 48.3,20.2 50.9,17.6 HDR2.92@50.9,16.5
SP9: HDR2.88 U1.B7 | length 22.6
  Bottom Layer w0.2: U1.B7@42.8,35.3 43.3,34.8 45.2,34.8 47.5,32.5 47.5,19.4 49.3,17.6 HDR2.88@49.3,16.5
SP10: HDR2.86 U1.A6 | length 20.5
  Bottom Layer w0.2: U1.A6@43.8,34.3 45.1,34.3 47.1,32.3 47.1,19 48.5,17.6 HDR2.86@48.5,16.5
SP11: HDR2.84 U1.B6 | length 21
  Bottom Layer w0.2: U1.B6@42.8,34.3 43.2,33.9 ; 43.101,33.999 43.3,33.8 44.3,33.8 44.4,33.9 44.9,33.9 46.7,32.1 46.7,18.6 47.7,17.6 HDR2.84@47.7,16.5
SP12: HDR2.82 U1.B5 | length 19.7
  Bottom Layer w0.2: U1.B5@42.8,33.3 43.3,32.8 44.1,32.8 44.2,32.7 45.5,32.7 46.3,31.9 46.3,18.2 46.9,17.6 HDR2.82@46.9,16.5
SP13: HDR2.80 U1.A4 | length 17.6
  Bottom Layer w0.2: U1.A4@43.8,32.3 45.3,32.3 45.93,31.67 45.93,17.77 46.1,17.6 HDR2.80@46.1,16.5
SP14: HDR2.78 U1.B4 | length 18.3
  Bottom Layer w0.2: U1.B4@42.8,32.3 43.1,32.3 43.6,31.8 44.2,31.8 44.3,31.9 45.2,31.9 45.5,31.6 45.5,17.8 45.3,17.6 HDR2.78@45.3,16.5
SP15: HDR2.76 U1.C5 | length 18.8
  MidLayer2 w0.2: v1@42.3,31.9 43.9,30.3 44.7,30.3 44.975,30.025 44.975,18.475 v1(44.5,18)
  Bottom Layer w0.2: U1.C5@41.8,33.3 42.3,32.8 v1@42.3,31.9 ; HDR2.76@44.5,16.5 44.5,16.6 v1(44.5,18)
  other v1: 42.3,31.8
SPI_CLK: HDR1.46 U1.J17 | length 30.8
  MidLayer2 w0.127: v1(35.3,44.8) 35.8,45.3 35.8,47.3
  MidLayer2 w0.2: v1(32.5,68.8) 32.5,68 30.6,66.1 30.6,54 32.3,52.3 34.7,52.3 35.8,51.2 35.8,47.3
  Bottom Layer w0.2: HDR1.46@32.5,67.3 v1(32.5,68.8) ; v1(35.3,44.8) U1.J17@35.8,45.3
SPI_DIN: HDR1.44 U1.J18 | length 30.4
  MidLayer2 w0.2: v1(31.7,69.3) 31.7,67.7 30.2,66.2 30.2,53.8 32.1,51.9 34.5,51.9 35.4,51 35.4,48.8 35.3,48.7 v1(35.3,45.8)
  Bottom Layer w0.2: HDR1.44@31.7,67.3 v1(31.7,69.3) ; v1(35.3,45.8) U1.J18@35.8,46.3
SPI_DOUT: HDR1.50 U1.H18 | length 28.6
  MidLayer2 w0.2: v1(34.1,68.8) 31.1,65.8 31.1,57.1 32.5,55.7 32.9,55.3 33.5,54.7 34.7,54.7 35.1,54.3 35.1,52.5 36.3,51.3 v1(36.3,46.8)
  Bottom Layer w0.2: HDR1.50@34.1,67.3 v1(34.1,68.8) ; v1@36.5,46.6 v1(36.3,46.8) U1.H18@36.8,46.3
SPI_MODE: HDR1.52 U1.H17 | length 30.5
  MidLayer2 w0.127: 36.8,46.3 36.8,47.3
  MidLayer2 w0.2: v1(34.9,69.3) 34.9,68.6 31.5,65.2 31.5,57.6 32.9,56.2 33.8,56.2 35.5,54.5 35.5,52.7 36.8,51.4 36.8,47.3 ; v1(36.3,45.8) 36.8,46.3
  Bottom Layer w0.127: HDR1.52@34.9,67.3 v1(34.9,69.3)
  Bottom Layer w0.2: v1(36.3,45.8) U1.H17@36.8,45.3
SPI_SEL: HDR1.48 U1.J15 | length 29.4
  MidLayer1 w0.127: 35.8,44.3 35.8,47.3
  MidLayer1 w0.2: v1(33.3,69.3) 33.3,59.4 35.8,56.9 35.8,47.3 ; v1(35.3,43.8) 35.8,44.3
  Bottom Layer w0.2: HDR1.48@33.3,67.3 v1(33.3,69.3) ; v1(35.3,43.8) U1.J15@35.8,43.3
SRAM0_A0: U1.A10 U3.5 | length 11.7
  Bottom Layer w0.2: U1.A10@43.8,38.3 44.4,38.3 ; 44.225,38.3 45.9,38.3 51,38.3 53.5,35.8 U3.5@54.3,35.8
SRAM0_A1: U1.B10 U3.4 | length 13.2
  Bottom Layer w0.2: U1.B10@42.8,38.3 43.3,37.8 ; 43.101,37.999 43.3,37.8 ; U3.4@54.4,35 53.5,35 50.7,37.8 43.3,37.8
SRAM0_A2: U1.A9 U3.3 | length 11.9
  Bottom Layer w0.2: U1.A9@43.8,37.3 50.4,37.3 53.5,34.2 U3.3@54.4,34.2
SRAM0_A3: U1.B9 U3.2 | length 13.2
  Bottom Layer w0.2: U1.B9@42.8,37.3 43.3,36.8 50.1,36.8 53.5,33.4 U3.2@54.4,33.4
SRAM0_A4: U1.A8 U3.1 | length 12.3
  Bottom Layer w0.2: U1.A8@43.8,36.3 44.4,36.3 ; 44.225,36.3 45.5,36.3 49.8,36.3 53.5,32.6 U3.1@54.4,32.6
SRAM0_A5: U1.C7 U3.44 | length 25.1
  MidLayer2 w0.2: v1(42.3,34.8) 53.2,34.8 55.4,32.6 v1(64.2,32.6)
  Bottom Layer w0.2: U1.C7@41.8,35.3 v1(42.3,34.8) v1@42.101,34.999 ; v1(64.2,32.6) U3.44@65.5,32.6
SRAM0_A6: U1.D7 U3.43 | length 28.8
  MidLayer2 w0.127: 41.8,35.3 42.8,35.3
  MidLayer2 w0.2: v1(41.3,34.8) 41.8,35.3 ; 42.8,35.3 53.3,35.3 55.2,33.4 v1(66.8,33.4)
  Bottom Layer w0.2: U1.D7@40.8,35.3 v1(41.3,34.8) v1@41.101,34.999 ; U3.43@65.5,33.4 v1(66.8,33.4)
SRAM0_A7: U1.E7 U3.42 | length 26.9
  MidLayer1 w0.127: 40.8,35.3 42.8,35.3
  MidLayer1 w0.2: v1(40.3,35.8) 40.8,35.3 ; 42.8,35.3 63.1,35.3 v1(64.2,34.2)
  Bottom Layer w0.2: U1.E7@39.8,35.3 v1(40.3,35.8) v1@40.101,35.601 ; v1(64.2,34.2) U3.42@65.5,34.2
SRAM0_A8: U1.B16 U3.18 | length 12.9
  Bottom Layer w0.2: U1.B16@42.8,44.3 43.3,43.8 44.3,43.8 44.4,43.7 51,43.7 53.5,46.2 U3.18@54.4,46.2
SRAM0_A9: U1.C12 U3.27 | length 29.4
  MidLayer2 w0.2: v1(42.3,39.8) 49.4,39.8 53,43.4 61.4,43.4 64.2,46.2 v1(66.8,46.2)
  Bottom Layer w0.2: U1.C12@41.8,40.3 v1(42.3,39.8) v1@42.101,39.999 ; U3.27@65.5,46.2 v1(66.8,46.2)
SRAM0_A10: U1.D12 U3.26 | length 28.2
  MidLayer2 w0.127: 41.8,40.3 42.8,40.3
  MidLayer2 w0.2: v1(41.3,39.8) 41.8,40.3 ; 42.8,40.3 49.3,40.3 52.8,43.8 61,43.8 v1(64.2,47)
  Bottom Layer w0.2: U1.D12@40.8,40.3 v1(41.3,39.8) v1@41.101,39.999 ; v1(64.2,47) U3.26@65.5,47
SRAM0_A11: U1.E13 U3.25 | length 32.6
  MidLayer1 w0.127: 40.8,40.3 42.8,40.3
  MidLayer1 w0.2: v1(40.3,40.8) 40.8,40.3 ; 42.8,40.3 53,40.3 53.6,39.7 57.6,39.7 64.1,46.2 65.2,46.2 v1(66.8,47.8)
  Bottom Layer w0.2: U1.E13@39.8,41.3 v1(40.3,40.8) v1@40.101,40.999 ; U3.25@65.5,47.8 v1(66.8,47.8)
SRAM0_A12: U1.C13 U3.24 | length 27.4
  MidLayer2 w0.2: v1(42.3,40.8) 49.2,40.8 52.6,44.2 59.8,44.2 v1(64.2,48.6)
  Bottom Layer w0.2: U1.C13@41.8,41.3 v1(42.3,40.8) v1@42.101,40.999 ; v1(64.2,48.6) U3.24@65.5,48.6
SRAM0_A13: U1.D13 U3.23 | length 31.4
  MidLayer2 w0.127: 41.8,41.3 42.8,41.3
  MidLayer2 w0.2: v1(41.3,40.8) 41.8,41.3 ; 42.8,41.3 49.1,41.3 52.4,44.6 59.3,44.6 64.1,49.4 v1(66.8,49.4)
  Bottom Layer w0.2: U1.D13@40.8,41.3 v1(41.3,40.8) v1@41.101,40.999 ; U3.23@65.5,49.4 v1(66.8,49.4)
  other v1: 41.3,40.8
SRAM0_A14: U1.B18 U3.22 | length 13.2
  Bottom Layer w0.2: U1.B18@42.8,46.3 43.3,46.8 ; 43.101,46.601 43.3,46.8 ; U3.22@54.4,49.4 53.5,49.4 51,46.9 44.3,46.9 44.2,46.8 43.3,46.8
SRAM0_A15: U1.C18 U3.21 | length 14.3
  Bottom Layer w0.2: U1.C18@41.8,46.3 42.3,45.8 ; 42.101,45.999 42.3,45.8 ; U3.21@54.4,48.6 53.5,48.6 50.6,45.7 45.5,45.7 44.3,45.7 44.2,45.8 42.3,45.8
SRAM0_A16: U1.A17 U3.20 | length 11.7
  Bottom Layer w0.2: U1.A17@43.8,45.3 44.3,45.3 ; 44.225,45.3 45.8,45.3 51,45.3 53.5,47.8 U3.20@54.4,47.8
SRAM0_A17: U1.B17 U3.19 | length 12.7
  Bottom Layer w0.2: U1.B17@42.8,45.3 43.1,45 ; 43.101,44.999 43.3,44.8 44.2,44.8 44.3,44.9 51.4,44.9 53.5,47 U3.19@54.4,47
SRAM0_A18: U1.E11 U3.28 | length 28.9
  MidLayer1 w0.127: 40.8,39.3 42.8,39.3
  MidLayer1 w0.2: v1(40.3,39.8) 40.8,39.3 ; 42.8,39.3 57.8,39.3 63.9,45.4 v1(64.2,45.4)
  Bottom Layer w0.2: U1.E11@39.8,39.3 v1(40.3,39.8) ; v1@40.101,39.601 v1(40.3,39.8) ; v1(64.2,45.4) U3.28@65.5,45.4
SRAM0_D0: U1.A11 U3.7 | length 11.6
  Bottom Layer w0.2: U1.A11@43.8,39.3 44.4,39.3 ; 44.225,39.3 51.2,39.3 51.6,39.3 53.5,37.4 U3.7@54.4,37.4
SRAM0_D1: U1.B12 U3.8 | length 12.8
  Bottom Layer w0.2: U1.B12@42.8,40.3 43.3,39.8 ; 43.101,39.999 43.3,39.8 ; U3.8@54.4,38.2 53.5,38.2 51.9,39.8 43.3,39.8
SRAM0_D2: U1.A12 U3.9 | length 11.2
  Bottom Layer w0.2: U1.A12@43.8,40.3 44.3,40.3 ; 44.225,40.3 52.2,40.3 53.5,39 U3.9@54.4,39
SRAM0_D3: U1.B13 U3.10 | length 12.5
  Bottom Layer w0.2: U1.B13@42.8,41.3 43.3,40.8 ; 43.101,40.999 43.3,40.8 ; U3.10@54.4,39.8 53.5,39.8 52.5,40.8 51.6,40.8 46.4,40.8 43.3,40.8
SRAM0_D4: U1.A13 U3.13 | length 10.9
  Bottom Layer w0.2: U1.A13@43.8,41.3 44.3,41.3 ; 44.225,41.3 52.6,41.3 53.5,42.2 U3.13@54.3,42.2
SRAM0_D5: U1.B14 U3.14 | length 12.3
  Bottom Layer w0.2: U1.B14@42.8,42.3 43.1,42 ; 43.101,41.999 43.3,41.8 46.3,41.8 52.3,41.8 53.5,43 U3.14@54.4,43
SRAM0_D6: U1.A14 U3.15 | length 11.4
  Bottom Layer w0.2: U1.A14@43.8,42.3 44.4,42.3 ; 44.225,42.3 52,42.3 53.5,43.8 U3.15@54.4,43.8
SRAM0_D7: U1.B15 U3.16 | length 12.7
  Bottom Layer w0.2: U1.B15@42.8,43.3 43.2,42.9 ; 43.101,42.999 43.3,42.8 46,42.8 51.7,42.8 53.5,44.6 U3.16@54.4,44.6
SRAM0_D8: U1.D11 U3.29 | length 30.2
  MidLayer2 w0.127: 41.8,39.3 42.8,39.3
  MidLayer2 w0.2: v1(41.3,38.8) 41.8,39.3 ; 42.8,39.3 49.5,39.3 53.2,43 62.3,43 63.9,44.6 v1(66.8,44.6)
  Bottom Layer w0.2: U1.D11@40.8,39.3 v1(41.3,38.8) v1@41.101,38.999 ; U3.29@65.5,44.6 v1(66.8,44.6)
SRAM0_D9: U1.E10 U3.30 | length 28.8
  MidLayer1 w0.127: 40.8,38.3 42.8,38.3
  MidLayer1 w0.2: v1(40.3,38.8) 40.8,38.3 ; 42.8,38.3 57.4,38.3 62.9,43.8 v1(64.2,43.8) v1@64.2,43.9
  Bottom Layer w0.2: U1.E10@39.8,38.3 40.3,38.8 v1@40.101,38.601 ; v1(64.2,43.8) U3.30@65.5,43.8
SRAM0_D10: U1.C11 U3.31 | length 28.5
  MidLayer2 w0.2: v1(42.3,38.8) 49.6,38.8 53.4,42.6 62.9,42.6 63.3,43 v1(66.8,43)
  Bottom Layer w0.2: U1.C11@41.8,39.3 v1(42.3,38.8) v1@42.101,38.999 ; U3.31@65.5,43 v1(66.8,43)
SRAM0_D11: U1.D10 U3.32 | length 27
  MidLayer2 w0.127: 41.8,38.3 42.8,38.3
  MidLayer2 w0.2: v1(41.3,37.8) 41.8,38.3 ; 42.8,38.3 49.8,38.3 53.7,42.2 v1@64.3,42.2
  Bottom Layer w0.2: U1.D10@40.8,38.3 v1(41.3,37.8) v1@41.101,37.999 ; v1@64.3,42.2 U3.32@65.5,42.2
  other v1: 64.2,42.2
SRAM0_D12: U1.C10 U3.35 | length 27.6
  MidLayer2 w0.2: v1(42.3,37.8) 62.4,37.8 64,39.4 66.4,39.4 v1(66.8,39.8)
  Bottom Layer w0.2: U1.C10@41.8,38.3 v1(42.3,37.8) v1@42.101,37.999 ; U3.35@65.5,39.8 v1(66.8,39.8)
SRAM0_D13: U1.E9 U3.36 | length 27.1
  MidLayer1 w0.127: 40.8,37.3 42.8,37.3
  MidLayer1 w0.2: v1(40.3,37.8) 40.8,37.3 ; 42.8,37.3 62.7,37.3 v1(64.2,38.8)
  Bottom Layer w0.2: U1.E9@39.8,37.3 v1(40.3,37.8) ; v1@40.101,37.601 v1(40.3,37.8) ; v1(64.2,38.8) 64.4,39 U3.36@65.5,39
SRAM0_D14: U1.D9 U3.37 | length 27.9
  MidLayer2 w0.127: 41.8,37.3 42.8,37.3
  MidLayer2 w0.2: v1(41.3,36.8) 41.8,37.3 ; 42.8,37.3 63,37.3 63.9,38.2 v1@66.7,38.2
  Bottom Layer w0.2: U1.D9@40.8,37.3 v1(41.3,36.8) ; U3.37@65.5,38.2 v1@66.7,38.2
  other v1: 66.8,38.2
SRAM0_D15: U1.C9 U3.38 | length 24.4
  MidLayer2 w0.2: v1(42.3,36.8) 63.6,36.8 v1(64.2,37.4)
  Bottom Layer w0.2: U1.C9@41.8,37.3 v1(42.3,36.8) v1@42.101,36.999 ; v1(64.2,37.4) U3.38@65.5,37.4
SRAM0_E: U1.B11 U3.6 | length 13
  Bottom Layer w0.2: U1.B11@42.8,39.3 43.3,38.8 ; 43.101,38.999 43.3,38.8 ; U3.6@54.4,36.6 53.5,36.6 51.3,38.8 43.3,38.8
SRAM0_LB: U1.E8 U3.39 | length 28.9
  MidLayer1 w0.127: 40.8,36.3 42.8,36.3
  MidLayer1 w0.2: v1(40.3,36.8) 40.8,36.3 ; 42.8,36.3 56.1,36.3 56.4,36.6 v1@66.7,36.6
  Bottom Layer w0.2: U1.E8@39.8,36.3 v1(40.3,36.8) v1@40.101,36.601 ; U3.39@65.5,36.6 v1@66.7,36.6
  other v1: 66.8,36.6
SRAM0_OE: TP1.1 U1.C8 U3.41 | length 34.8
  MidLayer2 w0.2: v1(42.3,35.8) 53.4,35.8 54.2,35 v1@66.7,35 ; TP1.1@63.3,30.1 64.9,30.1 67.5,32.7 67.5,34.3 v1(66.8,35)
  Bottom Layer w0.2: U1.C8@41.8,36.3 42.3,35.8 v1@42.101,35.999 ; U3.41@65.5,35 v1@66.7,35
SRAM0_UB: U1.D8 U3.40 | length 25.3
  MidLayer2 w0.127: 41.8,36.3 42.8,36.3
  MidLayer2 w0.2: v1(41.3,35.8) 41.8,36.3 ; 42.8,36.3 53.5,36.3 54,35.8 v1(64.2,35.8)
  Bottom Layer w0.2: U1.D8@40.8,36.3 v1(41.3,35.8) ; v1(64.2,35.8) U3.40@65.5,35.8
SRAM0_W: TP4.1 U1.A15 U3.17 | length 21.6
  Bottom Layer w0.2: U1.A15@43.8,43.3 44.3,43.3 ; 44.225,43.3 51.4,43.3 53.5,45.4 56.1,45.4 60,49.3 TP4.1@60,52.1
SRAM1_A0: U1.U8 U4.5 | length 26.4
  MidLayer2 w0.127: 25.8,37.3 26.8,37.3
  MidLayer2 w0.2: v1(5.3,42.3) 6.9,40.7 12.7,40.7 16.1,37.3 25.8,37.3 ; 26.8,37.3 v1(27.3,36.8)
  Bottom Layer w0.2: U4.5@3.9,42.3 v1(5.3,42.3) ; v1(27.3,36.8) U1.U8@27.8,36.3
SRAM1_A1: U1.V8 U4.4 | length 27.7
  MidLayer2 w0.2: v1(2.6,41.5) 5.5,41.5 6.7,40.3 12.5,40.3 16,36.8 v1(26.3,36.8)
  Bottom Layer w0.2: v1(2.6,41.5) U4.4@3.9,41.5 ; v1(26.3,36.8) U1.V8@26.8,36.3
SRAM1_A2: U1.T7 U4.3 | length 27.8
  MidLayer1 w0.127: 25.8,35.3 27.8,35.3
  MidLayer1 w0.2: v1(5.4,40.7) 8.9,40.7 10.1,39.5 13,39.5 17.2,35.3 25.8,35.3 ; 27.8,35.3 v1(28.3,34.8)
  Bottom Layer w0.2: U4.3@3.9,40.7 v1(5.4,40.7) ; v1@28.499,35 v1(28.3,34.8) U1.T7@28.8,35.3
SRAM1_A3: U1.U7 U4.2 | length 28.7
  MidLayer2 w0.127: 25.8,36.3 26.8,36.3
  MidLayer2 w0.2: v1(2.6,39.9) 12.3,39.9 15.9,36.3 25.8,36.3 ; 26.8,36.3 v1(27.3,35.8)
  Bottom Layer w0.2: v1(2.6,39.9) U4.2@3.925,39.9 ; v1@27.5,35.6 v1(27.3,35.8) U1.U7@27.8,35.3
SRAM1_A4: U1.V7 U4.1 | length 24.5
  MidLayer2 w0.2: v1(5.4,39.1) 12.5,39.1 15.8,35.8 v1(26.3,35.8)
  Bottom Layer w0.2: U4.1@3.9,39.1 v1(5.4,39.1) ; v1(26.3,35.8) U1.V7@26.8,35.3
SRAM1_A5: U1.Y8 U4.44 | length 10.9
  Bottom Layer w0.2: U4.44@15.075,39.1 17.9,39.1 20.7,36.3 24.375,36.3 ; 24.4,36.3 U1.Y8@24.8,36.3
SRAM1_A6: U1.W9 U4.43 | length 12.2
  Bottom Layer w0.2: U4.43@15.075,39.9 17.6,39.9 20.7,36.8 25.3,36.8 U1.W9@25.8,37.3
SRAM1_A7: U1.Y9 U4.42 | length 11.1
  Bottom Layer w0.2: U4.42@15.075,40.7 17.4,40.7 20.8,37.3 24.375,37.3 ; 24.4,37.3 U1.Y9@24.8,37.3
SRAM1_A8: U1.V13 U4.18 | length 29.3
  MidLayer2 w0.2: v1(5.3,52.7) 5.9,52.7 10.7,47.9 10.7,45 11.4,44.3 14.5,44.3 17,41.8 v1(26.3,41.8)
  Bottom Layer w0.2: U4.18@3.9,52.7 v1(5.3,52.7) ; v1(26.3,41.8) U1.V13@26.8,41.3
SRAM1_A9: U1.W16 U4.27 | length 15.3
  Bottom Layer w0.2: U4.27@15.1,52.7 15.9,52.7 21.4,47.2 21.4,46.1 23.8,43.7 24.3,43.7 24.4,43.8 25.3,43.8 U1.W16@25.8,44.3
SRAM1_A10: U1.W17 U4.26 | length 15.2
  Bottom Layer w0.2: U4.26@15.1,53.5 15.9,53.5 19.3,50.1 21.8,47.6 21.8,46.5 23.4,44.9 24.3,44.9 24.4,44.8 25.3,44.8 U1.W17@25.8,45.3
SRAM1_A11: U1.Y17 U4.25 | length 14.2
  Bottom Layer w0.2: U4.25@15.1,54.3 16,54.3 19.7,50.6 22.2,48.1 22.2,46.7 23.6,45.3 U1.Y17@24.8,45.3
SRAM1_A12: U1.W18 U4.24 | length 15.9
  Bottom Layer w0.2: U4.24@15.075,55.1 16,55.1 22.6,48.5 22.6,46.8 23.7,45.7 24.3,45.7 24.4,45.8 25.3,45.8 25.499,45.999 U1.W18@25.8,46.3
SRAM1_A13: U1.V18 U4.23 | length 16.5
  Bottom Layer w0.2: U4.23@15.1,55.9 15.9,55.9 23,48.8 23,47.7 23.8,46.9 24.4,46.9 24.5,46.8 26.3,46.8 26.5,46.6 ; 26.4,46.7 U1.V18@26.8,46.3
SRAM1_A14: U1.U14 U4.22 | length 31.6
  MidLayer2 w0.127: 25.8,43.3 26.8,43.3
  MidLayer2 w0.2: v1(5.3,55.9) 12,49.2 12,46.1 12.6,45.5 15.2,45.5 17.4,43.3 25.8,43.3 ; 26.8,43.3 v1(27.3,42.8)
  Bottom Layer w0.2: U4.22@3.925,55.9 v1(5.3,55.9) ; v1@27.5,42.6 v1(27.3,42.8) U1.U14@27.8,42.3
SRAM1_A15: U1.V15 U4.21 | length 32.8
  MidLayer2 w0.2: v1(2.6,55.1) 5.4,55.1 11.6,48.9 11.6,45.7 12.2,45.1 15,45.1 17.3,42.8 v1(26.3,42.8)
  Bottom Layer w0.2: v1(2.6,55.1) U4.21@4,55.1 ; v1(26.3,42.8) U1.V15@26.8,43.3
SRAM1_A16: U1.T10 U4.20 | length 37
  MidLayer1 w0.127: 25.8,38.3 27.8,38.3
  MidLayer1 w0.2: v1(5.3,54.3) 6.5,53.1 6.5,44.9 10.6,40.8 13.5,40.8 16,38.3 25.8,38.3 ; 27.8,38.3 v1(28.3,37.8)
  Bottom Layer w0.2: U4.20@3.925,54.3 v1(5.3,54.3) ; v1@28.5,37.999 v1(28.3,37.8) U1.T10@28.8,38.3
SRAM1_A17: U1.U13 U4.19 | length 33.2
  MidLayer2 w0.127: 25.8,42.3 26.8,42.3
  MidLayer2 w0.2: v1(2.6,53.5) 5.8,53.5 11.1,48.2 11.1,45.5 11.9,44.7 14.7,44.7 17.1,42.3 25.8,42.3 ; 26.8,42.3 v1(27.3,41.8)
  Bottom Layer w0.2: v1(2.6,53.5) U4.19@3.925,53.5 ; v1(27.3,41.8) U1.U13@27.8,41.3
SRAM1_A18: U1.Y15 U4.28 | length 13.8
  Bottom Layer w0.2: U4.28@15.1,51.9 15.9,51.9 21,46.8 21,45.9 23.6,43.3 24.375,43.3 ; 24.4,43.3 U1.Y15@24.8,43.3
SRAM1_D0: U1.V9 U4.7 | length 25.6
  MidLayer2 w0.2: v1(5.3,43.9) 8.1,41.1 12.9,41.1 16.2,37.8 v1(26.3,37.8)
  Bottom Layer w0.2: U4.7@3.9,43.9 v1(5.3,43.9) ; v1(26.3,37.8) U1.V9@26.8,37.3
SRAM1_D1: U1.U9 U4.8 | length 29.6
  MidLayer2 w0.127: 25.8,38.3 26.8,38.3
  MidLayer2 w0.2: v1(2.6,44.7) 5.4,44.7 8.6,41.5 13.1,41.5 16.3,38.3 25.8,38.3 ; 26.8,38.3 v1(27.3,37.8)
  Bottom Layer w0.2: v1(2.6,44.7) U4.8@3.9,44.7 ; v1(27.3,37.8) U1.U9@27.8,37.3
SRAM1_D2: U1.T9 U4.9 | length 28.7
  MidLayer1 w0.127: 25.8,37.3 27.8,37.3
  MidLayer1 w0.2: v1(5.3,45.5) 10.5,40.3 13.4,40.3 16.4,37.3 25.8,37.3 ; 27.8,37.3 v1(28.3,36.8)
  Bottom Layer w0.2: U4.9@3.9,45.5 v1(5.3,45.5) ; v1(28.3,36.8) U1.T9@28.8,37.3
SRAM1_D3: U1.V10 U4.10 | length 29.4
  MidLayer2 w0.2: v1(2.6,46.3) 2.8,46.1 5.6,46.1 6.1,45.6 6.1,44.6 8.8,41.9 13.3,41.9 16.4,38.8 v1(26.3,38.8)
  Bottom Layer w0.2: v1(2.6,46.3) U4.10@3.9,46.3 ; v1(26.3,38.8) U1.V10@26.8,38.3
